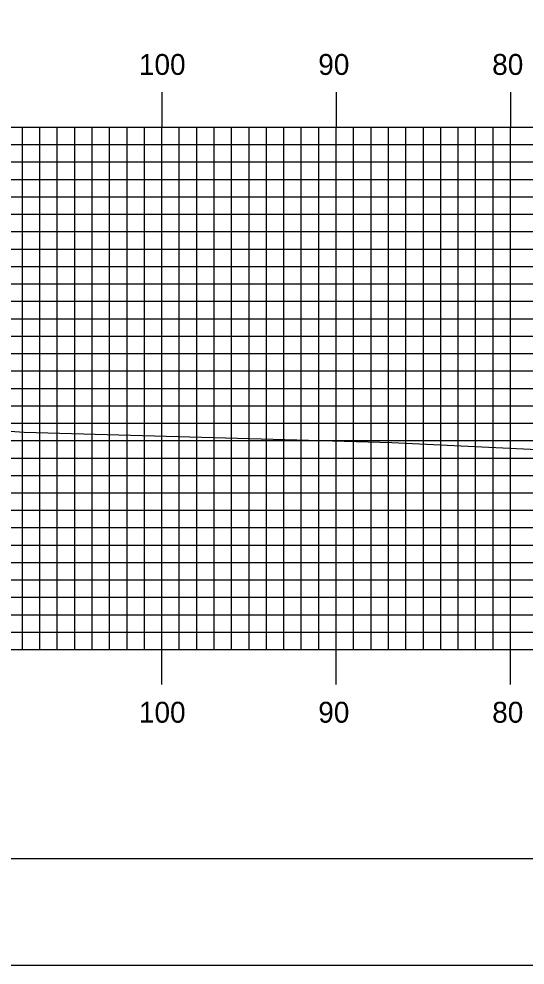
# Model space of a CAD drawing. Extents: x 1815702 to 1816046, y 442591 to 442811.
# Drawn here: x 1815759.8 to 1815788.9, y 442590.5 to 442644.9 of the extents above; entities that cross this region are included whole.
import ezdxf

# ---------------------------------------------------------------- set-up
doc = ezdxf.new("R2010")
doc.units = 0
for name, color, linetype in [('BORDER', 7, 'Continuous'), ('H_V ANNOTATION', 7, 'Continuous'), ('MAJOR', 7, 'Continuous'), ('MINOR', 7, 'Continuous'), ('PLOT BOUNDARY', 7, 'Continuous'), ('S_Roadway_Centerline', 7, 'Continuous')]:
    doc.layers.add(name, color=color, linetype=linetype)

msp = doc.modelspace()

# ---------------------------------------------------------------- linework, layer by layer
at = {"layer": 'BORDER'}
msp.add_lwpolyline([(1815718.447, 442596.665), (1816038.447, 442596.665), (1816038.447, 442806.665), (1815718.447, 442806.665)], close=True, dxfattribs=at)
at = {"layer": 'MAJOR'}
for p, q in [((1815768.047, 442640.669), (1815768.047, 442638.665)), ((1815778.047, 442640.669), (1815778.047, 442638.665)), ((1815788.047, 442640.669), (1815788.047, 442638.665)), ((1815728.047, 442638.665), (1816008.047, 442638.665)), ((1815728.047, 442638.665), (1816008.047, 442638.665)), ((1815768.047, 442608.665), (1815768.047, 442638.665)), ((1815778.047, 442608.665), (1815778.047, 442638.665)), ((1815788.047, 442608.665), (1815788.047, 442638.665)), ((1815728.047, 442633.665), (1816008.047, 442633.665)), ((1815728.047, 442628.665), (1816008.047, 442628.665)), ((1815728.047, 442623.665), (1816008.047, 442623.665)), ((1815728.047, 442618.665), (1816008.047, 442618.665)), ((1815728.047, 442613.665), (1816008.047, 442613.665)), ((1815728.047, 442608.665), (1816008.047, 442608.665)), ((1815728.047, 442608.665), (1816008.047, 442608.665)), ((1815768.047, 442606.661), (1815768.047, 442608.665)), ((1815778.047, 442606.661), (1815778.047, 442608.665)), ((1815788.047, 442606.661), (1815788.047, 442608.665))]:
    msp.add_line(p, q, dxfattribs=at)
at = {"layer": 'MINOR'}
for p, q in [((1815760.047, 442608.665), (1815760.047, 442638.665)), ((1815761.047, 442608.665), (1815761.047, 442638.665)), ((1815762.047, 442608.665), (1815762.047, 442638.665)), ((1815763.047, 442608.665), (1815763.047, 442638.665)), ((1815764.047, 442608.665), (1815764.047, 442638.665)), ((1815765.047, 442608.665), (1815765.047, 442638.665)), ((1815766.047, 442608.665), (1815766.047, 442638.665)), ((1815767.047, 442608.665), (1815767.047, 442638.665)), ((1815769.047, 442608.665), (1815769.047, 442638.665)), ((1815770.047, 442608.665), (1815770.047, 442638.665)), ((1815771.047, 442608.665), (1815771.047, 442638.665)), ((1815772.047, 442608.665), (1815772.047, 442638.665)), ((1815773.047, 442608.665), (1815773.047, 442638.665)), ((1815774.047, 442608.665), (1815774.047, 442638.665)), ((1815775.047, 442608.665), (1815775.047, 442638.665)), ((1815776.047, 442608.665), (1815776.047, 442638.665)), ((1815777.047, 442608.665), (1815777.047, 442638.665)), ((1815779.047, 442608.665), (1815779.047, 442638.665)), ((1815780.047, 442608.665), (1815780.047, 442638.665)), ((1815781.047, 442608.665), (1815781.047, 442638.665)), ((1815782.047, 442608.665), (1815782.047, 442638.665)), ((1815783.047, 442608.665), (1815783.047, 442638.665)), ((1815784.047, 442608.665), (1815784.047, 442638.665)), ((1815785.047, 442608.665), (1815785.047, 442638.665)), ((1815786.047, 442608.665), (1815786.047, 442638.665)), ((1815787.047, 442608.665), (1815787.047, 442638.665)), ((1815728.047, 442637.665), (1816008.047, 442637.665)), ((1815728.047, 442636.665), (1816008.047, 442636.665)), ((1815728.047, 442635.665), (1816008.047, 442635.665)), ((1815728.047, 442634.665), (1816008.047, 442634.665)), ((1815728.047, 442632.665), (1816008.047, 442632.665)), ((1815728.047, 442631.665), (1816008.047, 442631.665)), ((1815728.047, 442630.665), (1816008.047, 442630.665)), ((1815728.047, 442629.665), (1816008.047, 442629.665)), ((1815728.047, 442627.665), (1816008.047, 442627.665)), ((1815728.047, 442626.665), (1816008.047, 442626.665)), ((1815728.047, 442625.665), (1816008.047, 442625.665)), ((1815728.047, 442624.665), (1816008.047, 442624.665)), ((1815728.047, 442622.665), (1816008.047, 442622.665)), ((1815728.047, 442621.665), (1816008.047, 442621.665)), ((1815728.047, 442620.665), (1816008.047, 442620.665)), ((1815728.047, 442619.665), (1816008.047, 442619.665)), ((1815728.047, 442617.665), (1816008.047, 442617.665)), ((1815728.047, 442616.665), (1816008.047, 442616.665)), ((1815728.047, 442615.665), (1816008.047, 442615.665)), ((1815728.047, 442614.665), (1816008.047, 442614.665)), ((1815728.047, 442612.665), (1816008.047, 442612.665)), ((1815728.047, 442611.665), (1816008.047, 442611.665)), ((1815728.047, 442610.665), (1816008.047, 442610.665)), ((1815728.047, 442609.665), (1816008.047, 442609.665))]:
    msp.add_line(p, q, dxfattribs=at)
at = {"layer": 'PLOT BOUNDARY'}
msp.add_lwpolyline([(1815702.26, 442590.547), (1816042.26, 442590.547), (1816042.26, 442810.547), (1815702.26, 442810.547)], close=True, dxfattribs=at)
at = {"layer": 'S_Roadway_Centerline'}
msp.add_lwpolyline([(1815728.047, 442623.44), (1815737.786, 442623.104), (1815745.496, 442622.409), (1815755.598, 442621.467), (1815760.143, 442621.143), (1815771.693, 442620.832), (1815781.234, 442620.56), (1815789.2, 442620.166), (1815799.6, 442619.669), (1815805.507, 442619.474), (1815817.105, 442619.1)], dxfattribs=at)

# ---------------------------------------------------------------- texts
at = {"layer": 'H_V ANNOTATION'}
for s, p in [('100', (1815766.73, 442641.665)), ('90', (1815777.019, 442641.665)), ('80', (1815786.998, 442641.665)), ('100', (1815766.73, 442604.465)), ('90', (1815777.019, 442604.465)), ('80', (1815786.998, 442604.465))]:
    msp.add_text(s, height=1.2, dxfattribs=at).set_placement(p)

doc.saveas('drawing.dxf')
